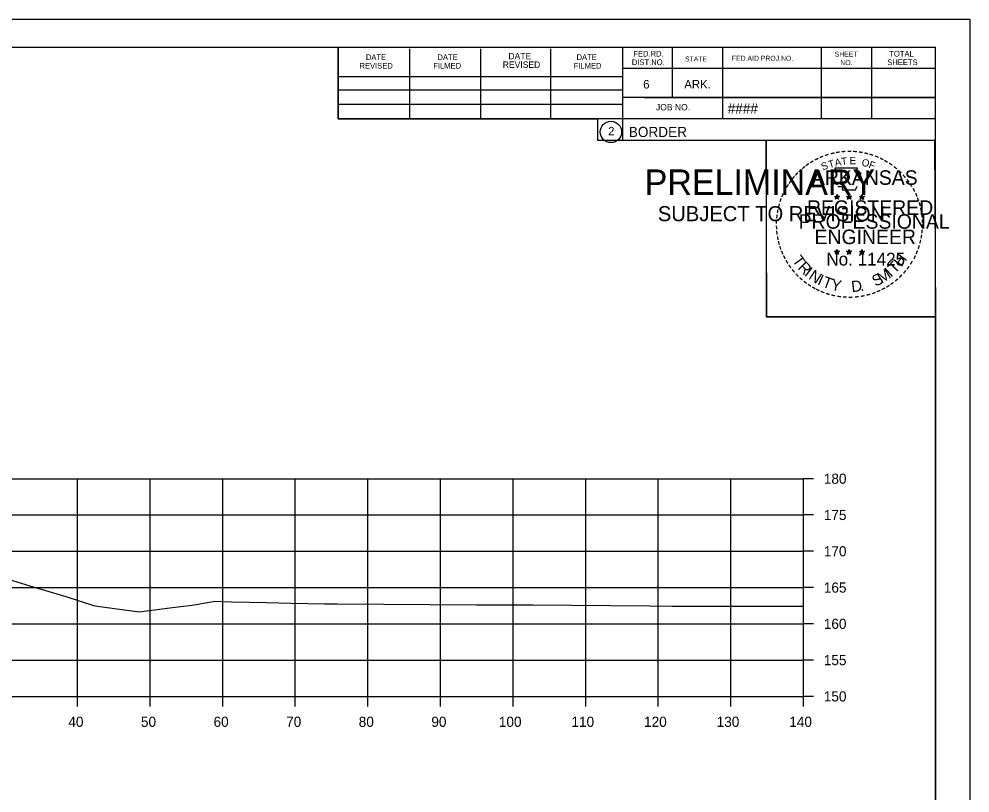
# Model space of a CAD drawing. Extents: x 1368503 to 1373085, y 379840 to 381833.
# Drawn here: x 1372954 to 1373085, y 381348.3 to 381455 of the extents above; entities that cross this region are included whole.
import ezdxf

# ---------------------------------------------------------------- set-up
doc = ezdxf.new("R2010")
doc.units = 0
for name, color, linetype in [('S_BRIDGE', 7, 'Continuous'), ('S_EDGE_PAVEMENT', 7, 'Continuous'), ('S_LANDSCAPING', 7, 'Continuous'), ('S_MISC_BOUNDARY', 7, 'Continuous'), ('S_MISC_BOUNDARY_ANNOT', 7, 'Continuous'), ('S_PHOTO_CENTERS', 7, 'Continuous'), ('S_PHOTO_NOTES', 7, 'Continuous'), ('S_TRAILS', 7, 'Continuous')]:
    doc.layers.add(name, color=color, linetype=linetype)

msp = doc.modelspace()

# ---------------------------------------------------------------- linework, layer by layer
at = {"layer": 'S_BRIDGE'}
for p, q in [((1372764.08, 381451.1), (1373080.26, 381451.1)), ((1372998, 381441.22), (1372998, 381451.1)), ((1373007.86, 381441.22), (1373007.86, 381450.9)), ((1373017.62, 381441.22), (1373017.62, 381450.9)), ((1373027.3, 381441.22), (1373027.3, 381450.9)), ((1373037.16, 381451.1), (1373037.16, 381438.3)), ((1373044, 381451.1), (1373044, 381444.16)), ((1373050.94, 381451.1), (1373050.94, 381441.22)), ((1373064.52, 381451.1), (1373064.52, 381441.22)), ((1373071.46, 381451.1), (1373071.46, 381441.22)), ((1373080.26, 381245.64), (1373080.26, 381451.1)), ((1373080.26, 381448.16), (1373037.16, 381448.16)), ((1373080.26, 381448.18), (1373080.26, 381448.18)), ((1372998, 381447.08), (1373037.16, 381447.08)), ((1372998, 381445.22), (1373037.16, 381445.22)), ((1373080.26, 381444.16), (1373037.16, 381444.16)), ((1373040.12, 381444.16), (1373080.26, 381444.16)), ((1372998, 381441.22), (1372998, 381443.28)), ((1372998, 381443.28), (1373037.16, 381443.28)), ((1373080.26, 381441.22), (1372998, 381441.22)), ((1373037.16, 381438.3), (1373080.26, 381438.3))]:
    msp.add_line(p, q, dxfattribs=at)
msp.add_circle((1373035.55, 381439.43), 1.47, dxfattribs=at)
at = {"layer": 'S_EDGE_PAVEMENT'}
for p, q in [((1373062.08, 381361.64), (1373062.08, 381391.64)), ((1373063.48, 381391.64), (1373062.08, 381391.64)), ((1373063.48, 381386.64), (1373062.08, 381386.64)), ((1373063.48, 381381.64), (1373062.08, 381381.64)), ((1373063.48, 381376.64), (1373062.08, 381376.64)), ((1373063.48, 381371.64), (1373062.08, 381371.64)), ((1373063.48, 381366.64), (1373062.08, 381366.64)), ((1372782.08, 381361.64), (1373062.08, 381361.64)), ((1372962.08, 381360.24), (1372962.08, 381361.64)), ((1372972.08, 381360.24), (1372972.08, 381361.64)), ((1372982.08, 381360.24), (1372982.08, 381361.64)), ((1372992.08, 381360.24), (1372992.08, 381361.64)), ((1373002.08, 381360.24), (1373002.08, 381361.64)), ((1373012.08, 381360.24), (1373012.08, 381361.64)), ((1373022.08, 381360.24), (1373022.08, 381361.64)), ((1373032.08, 381360.24), (1373032.08, 381361.64)), ((1373042.08, 381360.24), (1373042.08, 381361.64)), ((1373052.08, 381360.24), (1373052.08, 381361.64)), ((1373062.08, 381360.24), (1373062.08, 381361.64)), ((1373063.48, 381361.64), (1373062.08, 381361.64))]:
    msp.add_line(p, q, dxfattribs=at)
at = {"layer": 'S_LANDSCAPING'}
for p, q in [((1373066.7, 381430.81), (1373066.65, 381430.56)), ((1373066.7, 381430.44), (1373066.7, 381430.81)), ((1373066.7, 381430.81), (1373066.74, 381430.56)), ((1373068.37, 381430.81), (1373068.32, 381430.56)), ((1373068.37, 381430.44), (1373068.37, 381430.81)), ((1373068.37, 381430.81), (1373068.41, 381430.56)), ((1373070.13, 381430.8), (1373070.09, 381430.54)), ((1373070.13, 381430.43), (1373070.13, 381430.8)), ((1373070.13, 381430.8), (1373070.18, 381430.55)), ((1373066.35, 381430.55), (1373066.7, 381430.44)), ((1373066.35, 381430.55), (1373066.6, 381430.51)), ((1373066.35, 381430.55), (1373066.58, 381430.43)), ((1373066.48, 381430.15), (1373066.7, 381430.44)), ((1373066.48, 381430.15), (1373066.61, 381430.39)), ((1373066.48, 381430.15), (1373066.69, 381430.36)), ((1373066.91, 381430.15), (1373066.69, 381430.36)), ((1373067.04, 381430.55), (1373066.7, 381430.44)), ((1373066.91, 381430.15), (1373066.7, 381430.44)), ((1373067.04, 381430.55), (1373066.76, 381430.51)), ((1373066.91, 381430.15), (1373066.77, 381430.44)), ((1373067.04, 381430.55), (1373066.84, 381430.45)), ((1373068.02, 381430.55), (1373068.37, 381430.44)), ((1373068.02, 381430.55), (1373068.27, 381430.51)), ((1373068.02, 381430.55), (1373068.25, 381430.43)), ((1373068.15, 381430.15), (1373068.37, 381430.44)), ((1373068.15, 381430.15), (1373068.28, 381430.39)), ((1373068.15, 381430.15), (1373068.36, 381430.36)), ((1373068.58, 381430.15), (1373068.36, 381430.36)), ((1373068.71, 381430.55), (1373068.37, 381430.44)), ((1373068.58, 381430.15), (1373068.37, 381430.44)), ((1373068.71, 381430.55), (1373068.43, 381430.51)), ((1373068.58, 381430.15), (1373068.44, 381430.44)), ((1373068.71, 381430.55), (1373068.51, 381430.45)), ((1373069.78, 381430.54), (1373070.13, 381430.43)), ((1373069.78, 381430.54), (1373070.03, 381430.5)), ((1373069.78, 381430.54), (1373070.02, 381430.42)), ((1373069.91, 381430.13), (1373070.13, 381430.43)), ((1373069.91, 381430.13), (1373070.04, 381430.38)), ((1373069.91, 381430.13), (1373070.13, 381430.35)), ((1373070.48, 381430.54), (1373070.13, 381430.43)), ((1373070.34, 381430.13), (1373070.13, 381430.43)), ((1373070.34, 381430.13), (1373070.13, 381430.35)), ((1373070.48, 381430.54), (1373070.19, 381430.49)), ((1373070.34, 381430.13), (1373070.21, 381430.43)), ((1373070.48, 381430.54), (1373070.27, 381430.44)), ((1373066.34, 381422.98), (1373066.69, 381422.87)), ((1373066.34, 381422.98), (1373066.6, 381422.94)), ((1373066.34, 381422.98), (1373066.58, 381422.86)), ((1373066.48, 381422.57), (1373066.69, 381422.87)), ((1373066.48, 381422.57), (1373066.6, 381422.82)), ((1373066.48, 381422.57), (1373066.69, 381422.79)), ((1373066.69, 381423.24), (1373066.65, 381422.98)), ((1373066.69, 381422.87), (1373066.69, 381423.24)), ((1373066.69, 381423.24), (1373066.74, 381422.99)), ((1373067.04, 381422.98), (1373066.69, 381422.87)), ((1373066.9, 381422.57), (1373066.69, 381422.87)), ((1373066.9, 381422.57), (1373066.69, 381422.79)), ((1373067.04, 381422.98), (1373066.75, 381422.93)), ((1373066.9, 381422.57), (1373066.77, 381422.86)), ((1373067.04, 381422.98), (1373066.83, 381422.88)), ((1373068.01, 381422.98), (1373068.36, 381422.87)), ((1373068.01, 381422.98), (1373068.26, 381422.94)), ((1373068.01, 381422.98), (1373068.25, 381422.86)), ((1373068.14, 381422.57), (1373068.36, 381422.87)), ((1373068.14, 381422.57), (1373068.27, 381422.82)), ((1373068.14, 381422.57), (1373068.36, 381422.79)), ((1373068.36, 381423.24), (1373068.32, 381422.98)), ((1373068.36, 381422.87), (1373068.36, 381423.24)), ((1373068.36, 381423.24), (1373068.41, 381422.99)), ((1373068.71, 381422.98), (1373068.36, 381422.87)), ((1373068.57, 381422.57), (1373068.36, 381422.87)), ((1373068.57, 381422.57), (1373068.36, 381422.79)), ((1373068.71, 381422.98), (1373068.42, 381422.93)), ((1373068.57, 381422.57), (1373068.44, 381422.86)), ((1373068.71, 381422.98), (1373068.5, 381422.88)), ((1373069.78, 381422.97), (1373070.13, 381422.86)), ((1373069.78, 381422.97), (1373070.03, 381422.93)), ((1373069.78, 381422.97), (1373070.02, 381422.85)), ((1373069.91, 381422.56), (1373070.13, 381422.86)), ((1373069.91, 381422.56), (1373070.04, 381422.81)), ((1373069.91, 381422.56), (1373070.13, 381422.78)), ((1373070.13, 381423.23), (1373070.09, 381422.97)), ((1373070.13, 381422.86), (1373070.13, 381423.23)), ((1373070.13, 381423.23), (1373070.18, 381422.98)), ((1373070.47, 381422.97), (1373070.13, 381422.86)), ((1373070.34, 381422.56), (1373070.13, 381422.86)), ((1373070.34, 381422.56), (1373070.13, 381422.78)), ((1373070.47, 381422.97), (1373070.19, 381422.92)), ((1373070.34, 381422.56), (1373070.2, 381422.85)), ((1373070.47, 381422.97), (1373070.27, 381422.87))]:
    msp.add_line(p, q, dxfattribs=at)
for points in [[(1373066.39, 381434.43), (1373066.66, 381433.61)], [(1373069.9, 381433.51), (1373070.04, 381433.79), (1373069.36, 381433.77), (1373069.5, 381434.43), (1373066.39, 381434.43)], [(1373066.88, 381432.01), (1373066.88, 381431.92), (1373067.44, 381431.9), (1373067.39, 381431.43), (1373069.26, 381431.43), (1373069.46, 381431.97)], [(1373066.7, 381430.81), (1373066.91, 381430.15), (1373066.35, 381430.55), (1373067.04, 381430.55), (1373066.48, 381430.15), (1373066.7, 381430.81)], [(1373068.37, 381430.81), (1373068.58, 381430.15), (1373068.02, 381430.55), (1373068.71, 381430.55), (1373068.15, 381430.15), (1373068.37, 381430.81)], [(1373070.13, 381430.8), (1373070.34, 381430.13), (1373069.78, 381430.54), (1373070.48, 381430.54), (1373069.91, 381430.13), (1373070.13, 381430.8)], [(1373066.69, 381423.24), (1373066.9, 381422.57), (1373066.34, 381422.98), (1373067.04, 381422.98), (1373066.48, 381422.57), (1373066.69, 381423.24)], [(1373068.36, 381423.24), (1373068.57, 381422.57), (1373068.01, 381422.98), (1373068.71, 381422.98), (1373068.14, 381422.57), (1373068.36, 381423.24)], [(1373070.13, 381423.23), (1373070.34, 381422.56), (1373069.78, 381422.97), (1373070.47, 381422.97), (1373069.91, 381422.56), (1373070.13, 381423.23)]]:
    msp.add_lwpolyline(points, dxfattribs=at)
for centre, radius in [((1373066.69, 381430.44), 0.172), ((1373068.36, 381430.44), 0.172), ((1373070.13, 381430.43), 0.172), ((1373066.69, 381430.44), 0.145), ((1373066.69, 381430.44), 0.116), ((1373066.69, 381430.44), 0.0991), ((1373066.69, 381430.44), 0.0747), ((1373066.69, 381430.44), 0.0495), ((1373066.69, 381430.44), 0.0296), ((1373068.36, 381430.44), 0.145), ((1373068.36, 381430.44), 0.116), ((1373068.36, 381430.44), 0.0991), ((1373068.36, 381430.44), 0.0747), ((1373068.36, 381430.44), 0.0495), ((1373068.36, 381430.44), 0.0296), ((1373070.13, 381430.43), 0.145), ((1373070.13, 381430.43), 0.116), ((1373070.13, 381430.43), 0.0991), ((1373070.13, 381430.43), 0.0747), ((1373070.13, 381430.43), 0.0495), ((1373070.13, 381430.43), 0.0296), ((1373066.69, 381422.87), 0.172), ((1373066.69, 381422.87), 0.145), ((1373066.69, 381422.87), 0.116), ((1373066.69, 381422.87), 0.0991), ((1373066.69, 381422.87), 0.0747), ((1373066.69, 381422.87), 0.0495), ((1373066.69, 381422.87), 0.0296), ((1373068.36, 381422.87), 0.172), ((1373068.36, 381422.87), 0.145), ((1373068.36, 381422.87), 0.116), ((1373068.36, 381422.87), 0.0991), ((1373068.36, 381422.87), 0.0747), ((1373068.36, 381422.87), 0.0495), ((1373068.36, 381422.87), 0.0296), ((1373070.13, 381422.86), 0.172), ((1373070.13, 381422.86), 0.145), ((1373070.13, 381422.86), 0.116), ((1373070.13, 381422.86), 0.0991), ((1373070.13, 381422.86), 0.0747), ((1373070.13, 381422.86), 0.0495), ((1373070.13, 381422.86), 0.0296)]:
    msp.add_circle(centre, radius, dxfattribs=at)
at = {"layer": 'S_MISC_BOUNDARY'}
msp.add_lwpolyline([(1372951.27, 381378.17), (1372955.53, 381376.86), (1372960.49, 381375.39), (1372964.29, 381374.18), (1372964.82, 381374.08), (1372970.56, 381373.28), (1372974.79, 381373.83), (1372977.81, 381374.2), (1372980.53, 381374.66), (1372980.97, 381374.74), (1372983.28, 381374.68), (1372988.1, 381374.56), (1372991.56, 381374.5), (1372996.1, 381374.4), (1372997.89, 381374.38), (1373017.06, 381374.24), (1373024.82, 381374.24), (1373040.92, 381374.12), (1373044.06, 381374.09), (1373050.18, 381374.07), (1373062.08, 381374.05)], dxfattribs=at)
at = {"layer": 'S_PHOTO_CENTERS'}
for p, q in [((1372782.08, 381391.64), (1373062.08, 381391.64)), ((1372962.08, 381361.64), (1372962.08, 381391.64)), ((1372972.08, 381361.64), (1372972.08, 381391.64)), ((1372982.08, 381361.64), (1372982.08, 381391.64)), ((1372992.08, 381361.64), (1372992.08, 381391.64)), ((1373002.08, 381361.64), (1373002.08, 381391.64)), ((1373012.08, 381361.64), (1373012.08, 381391.64)), ((1373022.08, 381361.64), (1373022.08, 381391.64)), ((1373032.08, 381361.64), (1373032.08, 381391.64)), ((1373042.08, 381361.64), (1373042.08, 381391.64)), ((1373052.08, 381361.64), (1373052.08, 381391.64)), ((1373062.08, 381361.64), (1373062.08, 381391.64)), ((1372782.08, 381386.64), (1373062.08, 381386.64)), ((1372782.08, 381381.64), (1373062.08, 381381.64)), ((1372782.08, 381376.64), (1373062.08, 381376.64)), ((1372782.08, 381371.64), (1373062.08, 381371.64)), ((1372782.08, 381366.64), (1373062.08, 381366.64)), ((1372782.08, 381361.64), (1373062.08, 381361.64))]:
    msp.add_line(p, q, dxfattribs=at)
at = {"layer": 'S_PHOTO_NOTES'}
for p, q in [((1372751.68, 381454.99), (1373085.01, 381454.99)), ((1373056.3, 381415.84), (1373056.3, 381415.84))]:
    msp.add_line(p, q, dxfattribs=at)
for points in [[(1372751.67, 381454.99), (1373085.01, 381454.99), (1373085.01, 381241.66), (1372751.67, 381241.66)], [(1372998, 381451.1), (1372998, 381441.22), (1373033.73, 381441.22), (1373033.73, 381438.3), (1373056.93, 381438.3), (1373056.93, 381413.97), (1373080.26, 381413.97), (1373080.26, 381245.64), (1372764.08, 381245.64), (1372764.08, 381451.1)], [(1373056.93, 381438.3), (1373080.14, 381438.3), (1373080.26, 381413.97), (1373057.05, 381413.97)]]:
    msp.add_lwpolyline(points, close=True, dxfattribs=at)

# ---------------------------------------------------------------- texts
at = {"layer": 'S_BRIDGE'}
for s, height, p in [('DATE', 0.879, (1373021.44, 381449.44)), ('FED.RD.', 0.782, (1373038.64, 381449.82)), ('SHEET', 0.684, (1373066.38, 381449.82)), ('TOTAL', 0.782, (1373073.9, 381449.82)), ('REVISED', 0.782, (1373000.92, 381448.16)), ('DATE', 0.782, (1373001.8, 381449.34)), ('FILMED', 0.782, (1373011.08, 381448.16)), ('DATE', 0.782, (1373011.66, 381449.34)), ('REVISED', 0.879, (1373020.66, 381448.26)), ('FILMED', 0.782, (1373030.42, 381448.16)), ('DATE', 0.782, (1373030.82, 381449.34)), ('DIST.NO.', 0.782, (1373038.44, 381448.64)), ('STATE', 0.684, (1373045.76, 381449.14)), ('FED.AID PROJ.NO.', 0.684, (1373052.22, 381449.24)), ('NO.', 0.684, (1373067.16, 381448.64)), ('SHEETS', 0.782, (1373073.62, 381448.64)), ('6', 1.17, (1373040, 381445.42)), ('ARK.', 1.172, (1373045.66, 381445.42)), ('JOB NO.', 0.879, (1373041.76, 381442.4)), ('####', 1.4, (1373051.64, 381441.96)), ('2', 1.17, (1373035.17, 381438.95)), ('BORDER', 1.4, (1373038.02, 381438.73))]:
    msp.add_text(s, height=height, rotation=360, dxfattribs=at).set_placement(p)
at = {"layer": 'S_LANDSCAPING'}
for s, height, rotation, p in [('-', 1.6, 28.7918, (1373063.87, 381434.97)), ('-', 1.6, 24.3072, (1373064.5, 381435.29)), ('-', 1.6, 19.1761, (1373065.14, 381435.56)), ('-', 1.6, 13.6301, (1373065.89, 381435.8)), ('-', 1.6, 10.2193, (1373066.56, 381435.96)), ('T', 1, 6.0228, (1373067.33, 381434.86)), ('-', 1.6, 5.8968, (1373067.29, 381436.07)), ('-', 1.6, 0.1862, (1373068.06, 381436.14)), ('E', 1, 0.8323, (1373068.44, 381434.97)), ('-', 1.6, 357.743, (1373068.79, 381436.13)), ('-', 1.6, 352.1617, (1373069.53, 381436.08)), ('-', 1.6, 347.2049, (1373070.25, 381435.96)), ('-', 1.6, 342.3362, (1373070.89, 381435.81)), ('-', 1.6, 337.8551, (1373071.62, 381435.58)), ('-', 1.6, 334.1211, (1373072.25, 381435.31)), ('-', 1.6, 38.9507, (1373062.22, 381433.83)), ('-', 1.6, 36.2317, (1373062.69, 381434.21)), ('-', 1.6, 34.0636, (1373063.27, 381434.6)), ('S', 1, 21.594, (1373064.74, 381434.11)), ('T', 1, 16.4036, (1373065.66, 381434.44)), ('A', 1, 11.2132, (1373066.48, 381434.69)), ('O', 1, 350.4515, (1373070.04, 381434.76)), ('F', 1, 340.0707, (1373070.99, 381434.53)), ('-', 1.6, 329.6409, (1373072.83, 381435.03)), ('-', 1.6, 325.8627, (1373073.47, 381434.67)), ('-', 1.6, 320.5297, (1373074.08, 381434.24)), ('-', 1.6, 50.6142, (1373060.93, 381432.45)), ('-', 1.6, 48.423, (1373061.34, 381432.94)), ('-', 1.6, 42.9622, (1373061.78, 381433.41)), ('ARKANSAS', 2, 360, (1373063.24, 381432.14)), ('-', 1.6, 315.5786, (1373074.68, 381433.75)), ('-', 1.6, 309.8797, (1373075.25, 381433.2)), ('-', 1.6, 58.0706, (1373060.2, 381431.36)), ('-', 1.6, 54.2325, (1373060.52, 381431.88)), ('-', 1.6, 306.6522, (1373075.78, 381432.6)), ('-', 1.4, 303.6753, (1373076.26, 381432.03)), ('-', 1.6, 67.7743, (1373059.62, 381430.13)), ('-', 1.6, 62.8713, (1373059.88, 381430.74)), ('-', 1.6, 299.6684, (1373076.58, 381431.43)), ('-', 1.6, 294.6628, (1373076.91, 381430.82)), ('-', 1.6, 75.461, (1373059.21, 381428.79)), ('-', 1.6, 72.3945, (1373059.4, 381429.5)), ('REGISTERED', 2, 360, (1373062.56, 381428)), ('DWB', 0.01, 360, (1373066.68, 381430.44)), ('DWB', 0.01, 360, (1373068.35, 381430.44)), ('DWB', 0.01, 360, (1373070.12, 381430.43)), ('-', 1.6, 290.5728, (1373077.16, 381430.24)), ('-', 1.6, 285.1233, (1373077.4, 381429.66)), ('-', 1.6, 85.1863, (1373059, 381427.38)), ('-', 1.6, 81.2013, (1373059.08, 381428.07)), ('PROFESSIONAL', 2, 360, (1373061.41, 381426.09)), ('-', 1.6, 280.5493, (1373077.6, 381428.92)), ('-', 1.6, 276.5962, (1373077.76, 381428.15)), ('-', 1.6, 89.0622, (1373058.97, 381426.68)), ('-', 1.6, 274.3301, (1373077.82, 381427.43)), ('-', 1.6, 269.9407, (1373077.85, 381426.79)), ('-', 1.6, 94.1959, (1373059.01, 381425.96)), ('-', 1.6, 98.9479, (1373059.08, 381425.29)), ('ENGINEER', 2, 360, (1373063.6, 381423.97)), ('-', 1.6, 263.5172, (1373077.83, 381426.13)), ('-', 1.6, 101.7149, (1373059.22, 381424.56)), ('-', 1.6, 105.4578, (1373059.38, 381423.96)), ('-', 1.6, 255.7626, (1373077.65, 381424.8)), ('-', 1.6, 260.9953, (1373077.76, 381425.47)), ('-', 1.6, 109.0874, (1373059.59, 381423.33)), ('-', 1.6, 114.0643, (1373059.85, 381422.73)), ('No. 11425', 1.757, 360, (1373065.23, 381421.02)), ('DWB', 0.01, 360, (1373066.68, 381422.87)), ('DWB', 0.01, 360, (1373068.35, 381422.87)), ('DWB', 0.01, 360, (1373070.11, 381422.86)), ('-', 1.6, 247.8887, (1373077.25, 381423.4)), ('-', 1.6, 252.8681, (1373077.47, 381424.08)), ('-', 1.6, 115.7289, (1373060.15, 381422.12)), ('-', 1.6, 120.4471, (1373060.51, 381421.53)), ('T', 1.54, 306.0406, (1373060.45, 381421.71)), ('R', 1.54, 314.005, (1373061.21, 381420.66)), ('T', 1.54, 46.6444, (1373074.68, 381419.8)), ('H', 1.54, 54.6088, (1373075.57, 381420.74)), ('-', 1.6, 239.0712, (1373076.59, 381422.02)), ('-', 1.6, 244.6197, (1373076.99, 381422.77)), ('-', 1.6, 125.8934, (1373060.91, 381420.97)), ('-', 1.6, 130.7181, (1373061.37, 381420.42)), ('I', 1.54, 321.9694, (1373062.11, 381419.73)), ('N', 1.54, 326.5002, (1373062.68, 381419.26)), ('M', 1.54, 32.6563, (1373072.84, 381418.48)), ('I', 1.54, 42.1136, (1373074.12, 381419.32)), ('-', 1.6, 231.2538, (1373075.76, 381420.8)), ('-', 1.6, 233.8452, (1373076.19, 381421.37)), ('-', 1.6, 134.2238, (1373061.89, 381419.87)), ('-', 1.6, 138.9338, (1373062.42, 381419.41)), ('-', 1.6, 144.6463, (1373062.97, 381419)), ('I', 1.54, 335.3603, (1373063.89, 381418.47)), ('T', 1.54, 339.8912, (1373064.55, 381418.14)), ('Y', 1.54, 347.8556, (1373065.77, 381417.7)), ('D', 1.54, 6.3969, (1373068.75, 381417.34)), ('S', 1.54, 26.9312, (1373072, 381418.07)), ('-', 1.6, 221.0851, (1373074.76, 381419.73)), ('-', 1.6, 225.7653, (1373075.28, 381420.24)), ('-', 1.6, 148.0898, (1373063.53, 381418.63)), ('-', 1.6, 151.5704, (1373064.11, 381418.31)), ('-', 1.6, 154.6002, (1373064.63, 381418.06)), ('-', 1.6, 158.5612, (1373065.26, 381417.81)), ('.', 1.54, 13.7642, (1373069.94, 381417.47)), ('-', 1.6, 204.2516, (1373072.49, 381418.21)), ('-', 1.6, 207.3568, (1373073.12, 381418.53)), ('-', 1.6, 212.2491, (1373073.68, 381418.87)), ('-', 1.6, 215.7363, (1373074.21, 381419.26)), ('-', 1.6, 162.7983, (1373065.95, 381417.59)), ('-', 1.6, 167.5555, (1373066.66, 381417.43)), ('-', 1.6, 173.1155, (1373067.43, 381417.32)), ('-', 1.6, 176.5183, (1373068.18, 381417.27)), ('-', 1.6, 181.5918, (1373068.92, 381417.28)), ('-', 1.6, 185.8167, (1373069.73, 381417.36)), ('-', 1.6, 191.2858, (1373070.47, 381417.49)), ('-', 1.6, 195.4743, (1373071.2, 381417.69)), ('-', 1.6, 200.7184, (1373071.88, 381417.93))]:
    msp.add_text(s, height=height, rotation=rotation, dxfattribs=at).set_placement(p)
at = {"layer": 'S_MISC_BOUNDARY_ANNOT'}
for s, height, p in [('PRELIMINARY', 3.5, (1373040.21, 381430.76)), ('DWB', 0.01, (1373040.96, 381432.61)), ('SUBJECT TO REVISION', 2.0751, (1373042.02, 381427.13))]:
    msp.add_text(s, height=height, rotation=360, dxfattribs=at).set_placement(p)
at = {"layer": 'S_TRAILS'}
for s, p in [('180', (1373064.88, 381390.94)), ('175', (1373064.88, 381385.94)), ('170', (1373064.88, 381380.94)), ('165', (1373064.88, 381375.94)), ('160', (1373064.88, 381370.94)), ('155', (1373064.88, 381365.94)), ('150', (1373064.88, 381360.94)), ('40', (1372960.82, 381357.44)), ('50', (1372970.82, 381357.44)), ('60', (1372980.82, 381357.44)), ('70', (1372990.82, 381357.44)), ('80', (1373000.82, 381357.44)), ('90', (1373010.82, 381357.44)), ('100', (1373020.12, 381357.44)), ('110', (1373030.12, 381357.44)), ('120', (1373040.12, 381357.44)), ('130', (1373050.12, 381357.44)), ('140', (1373060.12, 381357.44))]:
    msp.add_text(s, height=1.4, dxfattribs=at).set_placement(p)

doc.saveas('drawing.dxf')
